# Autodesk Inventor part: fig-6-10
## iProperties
Created: 2004-05
Part Number: fig-6-10
Document SubType Name: Modeling
Designer: CADCIM Technologies
Manufacturer: Standard
Standards Organization: Custom
Author: CADCIM Technologies
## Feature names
1. Extrusion1
2. Hole1
3. Circular Pattern1
